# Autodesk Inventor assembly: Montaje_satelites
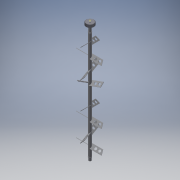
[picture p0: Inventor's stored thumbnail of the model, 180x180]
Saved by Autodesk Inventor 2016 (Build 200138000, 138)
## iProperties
Created: 2016-10
Part Number: Montaje_satelites
Document SubType Name: Assembly
Designer: Ingenieria
Author: Ingenieria
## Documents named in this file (7)
- C:\Users\ingenieria\Desktop\Project\Montaje_satelites.iam
- C:\Users\ingenieria\Desktop\Project\tubo_mecanico_satelites.ipt
- C:\Users\ingenieria\Desktop\Project\eje_inferior satelites.ipt
- C:\Users\ingenieria\Desktop\Project\eje_superior_satelites.ipt
- C:\Users\ingenieria\Desktop\Project\pala_1.ipt
- pala.ipt
- C:\Users\ingenieria\Desktop\Project\Spur Gears1.iam
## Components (20 placed, 5 different names)
1. tubo_mecanico_satelites:1 — Insert:1, Insert:2, Mate:1, Mate:2, Cylindrical:1, Cylindrical:2, Cylindrical:3, Cylindrical:4, Cylindrical:5, Cylindrical:6, Cylindrical:7, Cylindrical:8, Cylindrical:9, Cylindrical:10, Cylindrical:11, Cylindrical:12, Cylindrical:13, Cylindrical:14, Cylindrical:15, Cylindrical:16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
2. eje_inferior satelites:1 — Insert:2, Mate:19
3. eje_superior_satelites:1 — Insert:1, Mate:4, Mate:6, Mate:8, Mate:10, Mate:16, Mate:18
4. pala:1 — Cylindrical:2, Angle:1, Mate:3, Angle:2
5. pala:2 — Cylindrical:1, Angle:1, Mate:3, Mate:4
6. pala:3 — Cylindrical:3, Angle:3, Mate:5, Mate:6
7. pala:4 — Cylindrical:4, Angle:3, Mate:5, Angle:9
8. pala:5 — Cylindrical:5, Angle:5, Mate:7
9. pala:6 — Cylindrical:6, Angle:5, Mate:7, Mate:8, Angle:10
10. pala:7 — Cylindrical:7, Angle:7, Mate:9
11. pala:8 — Cylindrical:8, Angle:7, Mate:9, Mate:10, Angle:8, Flush:4
12. pala:9 — Cylindrical:9, Angle:11, Mate:11, Angle:12, Angle:16, Flush:1, Flush:4
13. pala:10 — Cylindrical:10, Angle:11, Mate:11
14. pala:11 — Cylindrical:12, Angle:13, Mate:12
15. pala:12 — Cylindrical:11, Angle:13, Mate:12, Angle:17, Flush:1, Flush:2
16. pala:13 — Cylindrical:14, Angle:14, Mate:13
17. pala:14 — Cylindrical:13, Angle:14, Mate:13, Angle:18, Flush:2, Flush:3
18. pala:15 — Cylindrical:16, Angle:15, Mate:14
19. pala:16 — Cylindrical:15, Angle:15, Mate:14, Angle:19, Flush:3
20. Spur Gears:1 [sub-assembly] — Mate:15, Mate:16, Mate:17
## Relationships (59: Mate 20, Angle 17, CylindricalJoint 16, Flush 4, Insert 2)
- Insert:1: tubo_mecanico_satelites:1 ↔ eje_superior_satelites:1
- Insert:2: tubo_mecanico_satelites:1 ↔ eje_inferior satelites:1
- Mate:1: tubo_mecanico_satelites:1
- Mate:2: tubo_mecanico_satelites:1
- Cylindrical:1: tubo_mecanico_satelites:1 ↔ pala:2
- Cylindrical:2: tubo_mecanico_satelites:1 ↔ pala:1
- Angle:1: pala:1 ↔ pala:2
- Mate:3: pala:1 ↔ pala:2
- Mate:4: eje_superior_satelites:1 ↔ pala:2
- Angle:2: pala:1
- Cylindrical:3: tubo_mecanico_satelites:1 ↔ pala:3
- Cylindrical:4: tubo_mecanico_satelites:1 ↔ pala:4
- Angle:3: pala:3 ↔ pala:4
- Mate:5: pala:3 ↔ pala:4
- Mate:6: eje_superior_satelites:1 ↔ pala:3
- Cylindrical:5: tubo_mecanico_satelites:1 ↔ pala:5
- Cylindrical:6: tubo_mecanico_satelites:1 ↔ pala:6
- Angle:5: pala:5 ↔ pala:6
- Mate:7: pala:5 ↔ pala:6
- Mate:8: eje_superior_satelites:1 ↔ pala:6
- Cylindrical:7: tubo_mecanico_satelites:1 ↔ pala:7
- Cylindrical:8: tubo_mecanico_satelites:1 ↔ pala:8
- Angle:7: pala:7 ↔ pala:8
- Mate:9: pala:7 ↔ pala:8
- Mate:10: eje_superior_satelites:1 ↔ pala:8
- Angle:8: pala:8
- Angle:9: pala:4
- Angle:10: pala:6
- Cylindrical:9: tubo_mecanico_satelites:1 ↔ pala:9
- Cylindrical:10: tubo_mecanico_satelites:1 ↔ pala:10
- Angle:11: pala:9 ↔ pala:10
- Mate:11: pala:9 ↔ pala:10
- Angle:12: pala:9
- Cylindrical:11: tubo_mecanico_satelites:1 ↔ pala:12
- Cylindrical:12: tubo_mecanico_satelites:1 ↔ pala:11
- Cylindrical:13: tubo_mecanico_satelites:1 ↔ pala:14
- Cylindrical:14: tubo_mecanico_satelites:1 ↔ pala:13
- Cylindrical:15: tubo_mecanico_satelites:1 ↔ pala:16
- Cylindrical:16: tubo_mecanico_satelites:1 ↔ pala:15
- Angle:13: pala:11 ↔ pala:12
- Mate:12: pala:11 ↔ pala:12
- Angle:14: pala:13 ↔ pala:14
- Mate:13: pala:13 ↔ pala:14
- Angle:15: pala:15 ↔ pala:16
- Mate:14: pala:15 ↔ pala:16
- Angle:16: pala:9
- Angle:17: pala:12
- Angle:18: pala:14
- Angle:19: pala:16
- Flush:1: pala:9 ↔ pala:12
- Flush:2: pala:12 ↔ pala:14
- Flush:3: pala:14 ↔ pala:16
- Flush:4: pala:8 ↔ pala:9
- Mate:15: Spur Gears:1
- Mate:16: eje_superior_satelites:1 ↔ Spur Gears:1
- Mate:17: Spur Gears:1
- Mate:18: eje_superior_satelites:1
- Mate:19: eje_inferior satelites:1
- Mate:20: tubo_mecanico_satelites:1
